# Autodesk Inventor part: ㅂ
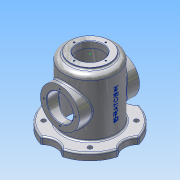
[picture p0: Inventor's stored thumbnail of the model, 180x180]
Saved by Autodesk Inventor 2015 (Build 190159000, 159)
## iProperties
Created: 2022-04
Part Number: ㅂ
Material: 알루미늄 6061
Document SubType Name: Modeling
Designer: User
Density: 2.7 g/cm^3
Appearance: 알루미늄 - 평지
Mass: 1510.28 g
Surface Area: 1244.17 cm^2
Volume: 559.364 cm^3
Author: User
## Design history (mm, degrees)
sketch "스케치1"
  geometry: 1 further point
sketch "스케치2"
  geometry: L1 (0, 0)-(-100, 0); L2 (0, 0)-(82, 0); L3 (0, 82)-(0, -82); L4 (0, 0)-(0, -100); A1 r 30 centre (-100, 0) between (-79.12, -21.541) and (-79.12, 21.541); A2 r 30 centre (100, 0) between (79.12, 21.541) and (79.12, -21.541); A3 r 30 centre (0, -100) between (21.541, -79.12) and (-21.541, -79.12); A4 r 30 centre (0, 100) between (-21.541, 79.12) and (21.541, 79.12); A5 r 82 centre (0, 0) between (79.12, 21.541) and (21.541, 79.12); A6 r 82 centre (0, 0) between (-21.541, 79.12) and (-79.12, 21.541); A7 r 82 centre (0, 0) between (-79.12, -21.541) and (-21.541, -79.12); A8 r 82 centre (0, 0) between (21.541, -79.12) and (79.12, -21.541); 1 further point
  constraints: 17 point on circle, 8 centre point, 8 end point, 3 coincident, 2 horizontal, 2 symmetric about line, 1 point on line, 2 other
  dimensions: "d1" = 100 distance of L1.start L1.end; "d2" = 60 diameter of A1; "d3" = 100 distance of L1.start L4.end; "d4" = 60 diameter of A3
extrude "돌출1" new body sketch "스케치2" distance "d5" = 14; taper "d6" = 0 deg
sketch "스케치3"
  geometry: L1 (-21.541, 14)-(21.541, 14) reference; L2 (-21.541, 14)-(-79.12, 14) reference; L3 (79.12, 14)-(21.541, 14) reference; L4 (0, 0)-(0, 137); L5 (-27, 137)-(-27, 124); L6 (-27, 124)-(-45, 124); L7 (-27, 137)-(-40, 137); L8 (-40, 137)-(-40, 132.606); L9 (-40, 132.606)-(-53, 132.606); L10 (-53, 132.606)-(-53, 14); L11 (-45, 124)-(-45, 14)
  constraints: 16 end point, 5 perpendicular, 3 vertical, 2 point on line, 1 horizontal
  dimensions: "d7" = 137 distance of L4.start L4.end; "d8" = 106 diameter of L9.end L4; "d9" = 80 diameter of L7.end L4; "d10" = 13 distance of L5.start L5.end; "d11" = 90 diameter of L11 L4; "d12" = 54 diameter of L5.start L4
revolve "회전1" sketch "스케치3" stored, may be unused: angle "d13" = 90 deg
sketch "스케치4"
  geometry: L1 (0, 0)-(0, 67.5); L2 (0, 0)-(-47.73, 47.73); L3 (-67.5, 0)-(67.5, 0); L4 (0, 0)-(0, -67.5); C1 r 4.5 at (-47.73, 47.73); C2 r 4.5 at (47.73, 47.73); C3 r 4.5 at (47.73, -47.73); C4 r 4.5 at (-47.73, -47.73); A1 r 67.5 centre (0, 0) between (0, 67.5) and (-47.73, 47.73); 1 further point
  constraints: 8 end point, 5 centre point, 5 point on circle, 3 symmetric about line, 2 coincident, 1 vertical, 3 other
  dimensions: "d14" = 135 diameter of A1; "d15" = 45 deg angle of L2 L1; "d16" = 9 diameter of C1
extrude "돌출2" cut sketch "스케치4" distance "d17" = 14; taper "d18" = 0 deg
sketch "스케치5"
  geometry: L1 (53, 14)-(53, 132.606) reference; L2 (-53, 14)-(-53, 132.606) reference; L3 (45, 14)-(-45, 14) reference; L4 (-21.541, 0)-(21.541, 0) reference; L5 (79.12, 0)-(21.541, 0) reference; L6 (-21.541, 0)-(-79.12, 0) reference; L7 (62, 68)-(-62, 68); L8 (0, 14)-(0, 95.311); 2 further points
  constraints: 4 end point, 2 midpoint, 1 horizontal, 1 point on line, 1 vertical
  dimensions: "d19" = 68 distance between parallel lines of L4 L7; "d20" = 124 distance of L7.start L7.end
node "작업 평면1"
sketch "스케치6"
  geometry: C1 r 40 at (0, 0); 1 further point
  constraints: 1 centre point
  dimensions: "d21" = 80 diameter of C1
extrude "돌출3" join sketch "스케치6" stored distance "d22" = 14; taper "d23" = 0 deg
sketch "스케치7"
  geometry: 1 further point
sketch "스케치8"
  geometry: C1 r 27 at (0, 0); 1 further point
  constraints: 1 centre point
  dimensions: "d24" = 54 diameter of C1
extrude "돌출4" cut sketch "스케치8" stored distance "d25" = 14; taper "d26" = 0 deg
sketch "스케치9" dims "d27" = 65
  geometry: C1 r 27 at (0, 0) reference; 3 further points
  constraints: 1 coincident, 1 horizontal alignment, 2 other
hole "구멍1" sketch "스케치9" at (-32.5, 0) diameter "d28" = 3.242; stored, may be unused: countersink angle "d32" = 90 deg, drill point angle "d34" = 118 deg; dims "d29" = 8, "d30" = 4, "d31" = 2, "d33" = 10
sketch "스케치10"
  geometry: 1 further point
sketch "스케치11" dims "d38" = 65
  geometry: 3 further points
  constraints: 1 coincident, 1 vertical alignment, 2 other
hole "구멍2" sketch "스케치11" at (0, 32.5) diameter "d39" = 3.242; stored, may be unused: countersink angle "d43" = 90 deg, drill point angle "d45" = 118 deg; dims "d40" = 8, "d41" = 4, "d42" = 2, "d44" = 10
node "작업 평면2"
sketch "스케치12"
  geometry: L1 (-21.541, 0)-(21.541, 0) reference; L2 (0, 0)-(0, 184.795); 1 further point
  constraints: 2 end point, 1 point on line, 1 vertical, 1 other
  dimensions: "d50" = 70 distance from line of L1 point (0, 70)
feature "엠보싱1" sketch "스케치12" dims "d1" = 100, "d2" = 60, "d3" = 100, "d4" = 60, "d51" = 0.5, "d52" = 0
fillet "모깎기1" dims "d53" = 10
sketch "스케치13"
  geometry: C1 r 45 at (0, 0); 1 further point
  constraints: 1 centre point, 1 coincident
  dimensions: "d54" = 90 diameter of C1
extrude "돌출5" cut sketch "스케치13" distance "d55" = 20; taper "d56" = 0 deg
fillet "모깎기2" dims "d57" = 3
fillet "모깎기3" dims "d58" = 3
fillet "모깎기4" dims "d59" = 3
chamfer "모따기1" distance "d60" = 1; stored, may be unused: second distance "d61" = 2, angle "d62" = 45 deg
fillet "모깎기5" dims "d63" = 3
chamfer "모따기2" distance "d64" = 1; stored, may be unused: second distance "d65" = 2, angle "d66" = 45 deg
node "솔리드1"
pattern_circular "원형 패턴1" dims angle "d36" = 360 deg
mirror "대칭1"
pattern_circular "원형 패턴2" dims angle "d47" = 360 deg
other parameters: "d0" = 164, "d49" = -58.5
